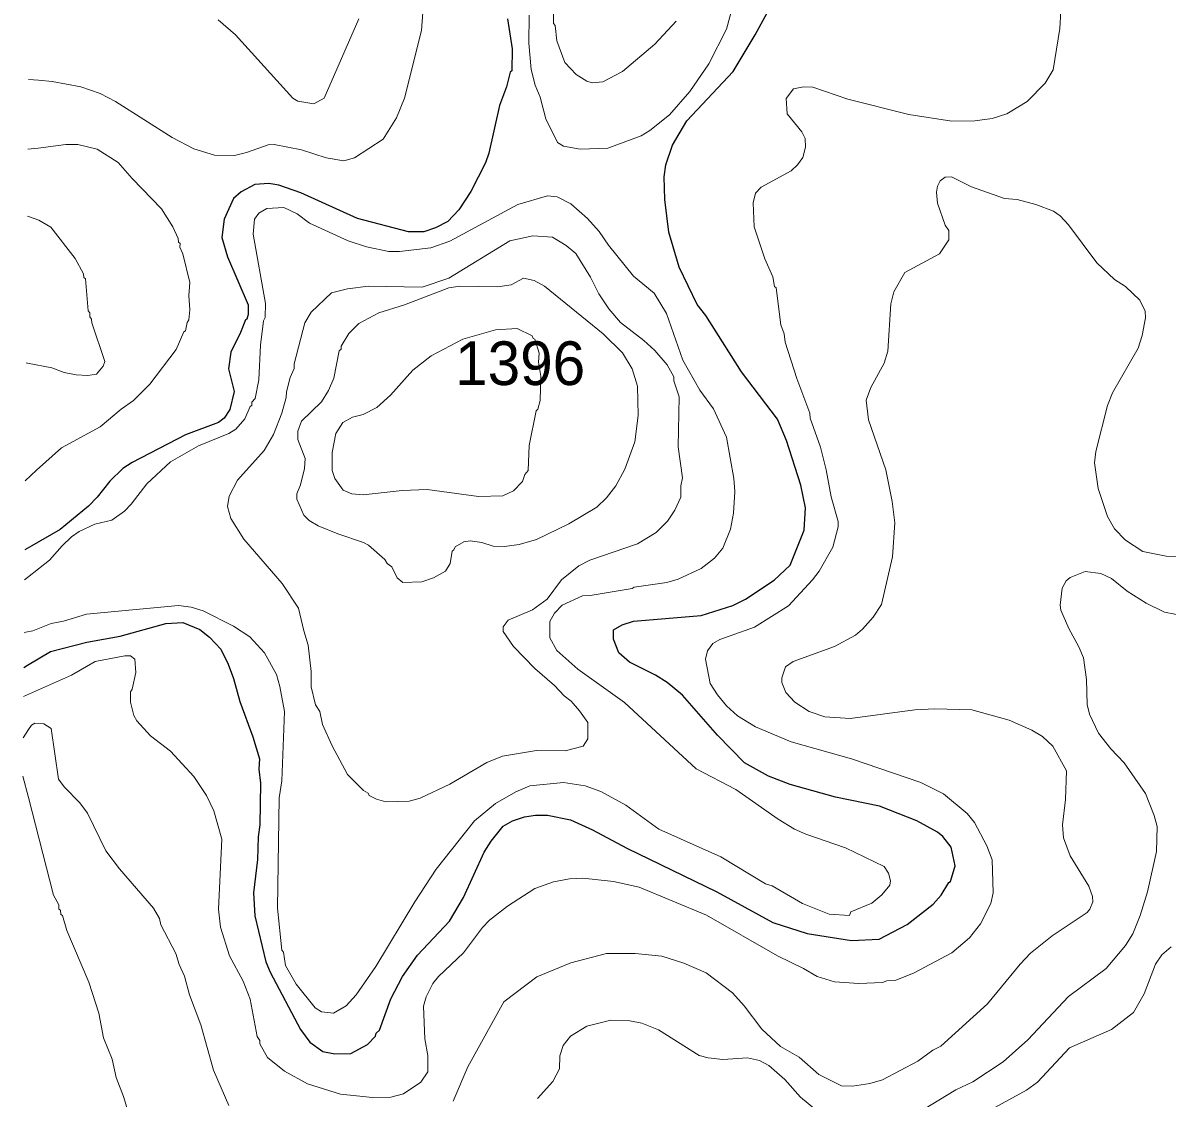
# Model space of a CAD drawing. Extents: x 598.3 to 623.2, y 6902.2 to 6930.1.
# Drawn here: x 598.471 to 600.565, y 6919.535 to 6921.503 of the extents above; entities that cross this region are included whole.
import ezdxf

# ---------------------------------------------------------------- set-up
doc = ezdxf.new("R2010")
doc.units = 0
doc.header["$LTSCALE"] = 0.032
doc.layers.add('1', color=7, linetype='Continuous', lineweight=25)
doc.layers.add('2', color=7, linetype='Continuous', lineweight=13)
doc.layers.add('21', color=7, linetype='Continuous')

msp = doc.modelspace()

# ---------------------------------------------------------------- linework, layer by layer
at = {"layer": '1'}
for points in [[(599.8109, 6921.4817), (599.8655, 6921.5827)], [(599.3574, 6921.5108), (599.3664, 6921.4558), (599.3655, 6921.4154), (599.3623, 6921.413), (599.3559, 6921.3862), (599.3429, 6921.3522), (599.3235, 6921.2647), (599.3172, 6921.2473), (599.2904, 6921.1951), (599.2686, 6921.1611), (599.2484, 6921.1399), (599.2259, 6921.128), (599.2046, 6921.1211), (599.1763, 6921.121), (599.0829, 6921.1452), (598.9791, 6921.1926), (598.9394, 6921.2067), (598.9206, 6921.2094), (598.8952, 6921.2078), (598.8704, 6921.1942), (598.8564, 6921.1818), (598.8389, 6921.1439), (598.8346, 6921.1103), (598.8449, 6921.0753), (598.8831, 6920.9876), (598.8831, 6920.9698), (598.8808, 6920.9614), (598.8783, 6920.9599), (598.8691, 6920.937), (598.851, 6920.9009), (598.8468, 6920.8705), (598.8573, 6920.8288), (598.8496, 6920.796), (598.839, 6920.78), (598.8288, 6920.7719), (598.7681, 6920.7496), (598.6706, 6920.6985), (598.6535, 6920.6875), (598.6297, 6920.6646), (598.6067, 6920.6352), (598.5906, 6920.6191), (598.5388, 6920.5762), (598.4873, 6920.5465), (598.4741, 6920.5389)], [(598.4723, 6920.3238), (598.4791, 6920.3278), (598.5212, 6920.3528), (598.5875, 6920.3701), (598.6486, 6920.3806), (598.7323, 6920.4041), (598.7633, 6920.4056), (598.7943, 6920.3933), (598.8125, 6920.3789), (598.8328, 6920.3571), (598.8465, 6920.3298), (598.8562, 6920.3036), (598.8676, 6920.261), (598.8915, 6920.1968), (598.904, 6920.1561), (598.9026, 6920.1373), (598.9058, 6920.1118), (598.9042, 6920.0354), (598.901, 6920.0133), (598.9001, 6919.9722), (598.8929, 6919.9113), (598.8952, 6919.8692), (598.9154, 6919.785), (598.9232, 6919.766), (598.979, 6919.6611), (598.9958, 6919.6379), (599.0197, 6919.6208), (599.0414, 6919.6164), (599.0707, 6919.6171), (599.1016, 6919.6334), (599.116, 6919.6485), (599.1172, 6919.6543), (599.1231, 6919.6594), (599.1439, 6919.717), (599.1652, 6919.7579), (599.1931, 6919.7968), (599.2516, 6919.8594), (599.2772, 6919.9027), (599.3152, 6919.9852), (599.3279, 6920.0058), (599.3494, 6920.0332), (599.367, 6920.0428), (599.3885, 6920.0503), (599.4089, 6920.0534), (599.4306, 6920.0534), (599.4727, 6920.0444), (599.5132, 6920.0266), (599.576, 6919.9927), (599.7409, 6919.9128), (599.8434, 6919.8566), (599.906, 6919.8366), (599.9869, 6919.8236), (600.0377, 6919.8261), (600.089, 6919.8534), (600.1364, 6919.8903), (600.1515, 6919.9069), (600.1653, 6919.9302), (600.1686, 6919.9316), (600.1766, 6919.9604), (600.1694, 6919.9949), (600.1542, 6920.0144), (600.1448, 6920.022), (600.1065, 6920.0428), (600.0387, 6920.0697), (599.9578, 6920.0859), (599.8752, 6920.1094), (599.835, 6920.1247), (599.7916, 6920.1489), (599.7417, 6920.1998), (599.6778, 6920.273), (599.6498, 6920.2959), (599.6285, 6920.3096), (599.5811, 6920.3333), (599.5615, 6920.3506), (599.5518, 6920.3756), (599.5519, 6920.3925), (599.5677, 6920.4014), (599.5883, 6920.4086), (599.7123, 6920.4186), (599.7703, 6920.437), (599.7932, 6920.4487), (599.8455, 6920.4832), (599.8747, 6920.5109), (599.9006, 6920.5748), (599.903, 6920.6155), (599.8942, 6920.657), (599.8685, 6920.7392), (599.8516, 6920.7781), (599.7859, 6920.8647), (599.7203, 6920.9679), (599.7049, 6920.9882), (599.6718, 6921.0565), (599.653, 6921.1201), (599.6457, 6921.18), (599.6441, 6921.2216), (599.6473, 6921.2437), (599.6594, 6921.2798), (599.6856, 6921.3239), (599.7705, 6921.4145), (599.8109, 6921.4817)]]:
    msp.add_lwpolyline(points, dxfattribs=at)
at = {"layer": '2'}
for points in [[(598.4811, 6921.3996), (598.4993, 6921.3988), (598.524, 6921.3964), (598.5767, 6921.3861), (598.6123, 6921.374), (598.6405, 6921.3598), (598.7441, 6921.2934), (598.7833, 6921.2731), (598.8213, 6921.2613), (598.8578, 6921.2605), (598.8801, 6921.2661), (598.9194, 6921.2805), (598.9307, 6921.2806), (598.9805, 6921.2709), (599.0257, 6921.2563), (599.058, 6921.2507), (599.0777, 6921.2565), (599.1303, 6921.2908), (599.1545, 6921.3298), (599.1694, 6921.3658), (599.2004, 6921.4896), (599.2069, 6921.5804)], [(600.3701, 6921.5249), (600.3686, 6921.493), (600.3563, 6921.4176), (600.3417, 6921.3931), (600.3085, 6921.3597), (600.2717, 6921.3372), (600.2449, 6921.3285), (600.2129, 6921.3244), (600.1709, 6921.3236), (600.0923, 6921.3357), (599.9805, 6921.3641), (599.9166, 6921.3857), (599.8993, 6921.3866), (599.8811, 6921.3828), (599.8675, 6921.3649), (599.8695, 6921.3367), (599.8962, 6921.3038), (599.9022, 6921.2919), (599.9029, 6921.2757), (599.8983, 6921.2568), (599.8886, 6921.2436), (599.8769, 6921.2327), (599.8216, 6921.2025), (599.8116, 6921.1916), (599.8075, 6921.1738), (599.8092, 6921.1299), (599.8285, 6921.0718), (599.8435, 6921.0385), (599.8465, 6921.0208), (599.8495, 6921.0184), (599.8578, 6920.9505), (599.864, 6920.9345), (599.8656, 6920.9189), (599.887, 6920.8527), (599.911, 6920.7891), (599.9113, 6920.7799), (599.9306, 6920.7267), (599.941, 6920.6854), (599.95, 6920.6361), (599.9629, 6920.5909), (599.9629, 6920.5807), (599.953, 6920.5435), (599.928, 6920.5001), (599.9159, 6920.4841), (599.8716, 6920.4365), (599.8097, 6920.3975), (599.746, 6920.3748), (599.7331, 6920.3675), (599.7234, 6920.3538), (599.7202, 6920.3387), (599.7284, 6920.2942), (599.7419, 6920.2734), (599.7587, 6920.2536), (599.7788, 6920.2351), (599.8116, 6920.2148), (599.8766, 6920.1872), (599.987, 6920.1563), (600.1143, 6920.1129), (600.1556, 6920.0923), (600.1987, 6920.0564), (600.2124, 6920.0395), (600.2348, 6919.9971), (600.2445, 6919.9717), (600.2464, 6919.9109), (600.2424, 6919.8917), (600.2235, 6919.8541), (600.203, 6919.8288), (600.171, 6919.8014), (600.1009, 6919.7638), (600.0682, 6919.7515), (600.052, 6919.7499), (600.0439, 6919.7467), (600.0008, 6919.7451), (599.956, 6919.7483), (599.9246, 6919.7578), (599.8993, 6919.7728), (599.8515, 6919.7959), (599.722, 6919.8704), (599.5984, 6919.9216), (599.5515, 6919.9321), (599.4957, 6919.9377), (599.4711, 6919.9369), (599.4419, 6919.9313), (599.4074, 6919.9189), (599.3576, 6919.8869), (599.3247, 6919.8611), (599.3117, 6919.8474)], [(599.397, 6921.5177), (599.3964, 6921.4663), (599.4012, 6921.4183), (599.4084, 6921.3894), (599.4175, 6921.3676), (599.4278, 6921.3279), (599.4492, 6921.2844), (599.4602, 6921.2778), (599.4908, 6921.2725), (599.5411, 6921.274), (599.6021, 6921.297), (599.6179, 6921.3064), (599.6538, 6921.3351), (599.6915, 6921.3776), (599.726, 6921.4287), (599.7587, 6921.4922), (599.7687, 6921.5303)], [(599.4416, 6921.5254), (599.4417, 6921.5025), (599.4448, 6921.4989), (599.4476, 6921.4703), (599.4623, 6921.431), (599.4835, 6921.4087), (599.5029, 6921.3965), (599.5127, 6921.394), (599.5318, 6921.3954), (599.568, 6921.4145), (599.6274, 6921.4647), (599.666, 6921.5065)], [(598.828, 6921.5089), (598.86, 6921.4818), (598.9647, 6921.3657), (598.9739, 6921.3599), (599.0033, 6921.3553), (599.0223, 6921.3659), (599.0856, 6921.5111)], [(598.48, 6921.272), (598.4987, 6921.2743), (598.5494, 6921.2806), (598.5712, 6921.2807), (598.6065, 6921.2724), (598.6449, 6921.2476), (598.6704, 6921.2183), (598.7243, 6921.1633), (598.7453, 6921.1303), (598.7551, 6921.1087), (598.7552, 6921.102), (598.7583, 6921.0998), (598.7577, 6921.093), (598.7632, 6921.0805), (598.7762, 6921.0281), (598.7746, 6921.0042), (598.7763, 6920.9779), (598.7746, 6920.9596), (598.7714, 6920.9553), (598.7683, 6920.9396), (598.7652, 6920.9381), (598.7514, 6920.9055), (598.7029, 6920.8424), (598.6734, 6920.812), (598.6504, 6920.7961), (598.6121, 6920.7643), (598.5411, 6920.7258), (598.4956, 6920.6849), (598.4751, 6920.6654)], [(600.7368, 6920.5253), (600.563, 6920.5271), (600.5205, 6920.5357), (600.4889, 6920.5563), (600.4687, 6920.5775), (600.4556, 6920.5998), (600.4389, 6920.6509), (600.4317, 6920.6979), (600.4341, 6920.7191), (600.4558, 6920.8028), (600.4651, 6920.8263), (600.5117, 6920.9083), (600.5192, 6920.9315), (600.5255, 6920.9638), (600.5247, 6920.976), (600.5149, 6920.996), (600.4889, 6921.021), (600.4686, 6921.0339), (600.4359, 6921.0643), (600.3846, 6921.1336), (600.3689, 6921.15), (600.3569, 6921.1589), (600.3246, 6921.1712), (600.2906, 6921.1801), (600.2671, 6921.1819), (600.2069, 6921.2032), (600.1701, 6921.2215), (600.1587, 6921.2209), (600.1492, 6921.2141), (600.1444, 6921.2047), (600.1426, 6921.1933), (600.1443, 6921.1736), (600.1588, 6921.1333), (600.1653, 6921.1233), (600.1653, 6921.1061), (600.1485, 6921.081), (600.0847, 6921.0468), (600.0646, 6921.0109), (600.0592, 6920.9889), (600.0535, 6920.9028), (600.0471, 6920.8807), (600.0223, 6920.836), (600.014, 6920.8127), (600.0185, 6920.777), (600.0503, 6920.6851), (600.0619, 6920.6271), (600.0665, 6920.5883), (600.062, 6920.5261)], [(598.4736, 6920.4838), (598.4792, 6920.4882), (598.5197, 6920.5198), (598.5423, 6920.5465), (598.5594, 6920.5628), (598.5737, 6920.5722), (598.6025, 6920.5859), (598.6337, 6920.5934), (598.6567, 6920.6099), (598.6691, 6920.6223), (598.6977, 6920.6597), (598.7406, 6920.7002), (598.7918, 6920.7291), (598.8475, 6920.752), (598.8603, 6920.76), (598.8766, 6920.7787), (598.8864, 6920.8012), (598.8895, 6920.8033), (598.8896, 6920.8094), (598.896, 6920.8162), (598.9025, 6920.8498), (598.9056, 6920.9138), (598.911, 6920.9583), (598.9139, 6920.964), (598.9146, 6920.9895), (598.8922, 6921.1167), (598.8945, 6921.1443), (598.9027, 6921.1551), (598.9172, 6921.1636), (598.9483, 6921.1656), (598.9727, 6921.1537), (598.9954, 6921.137), (599.0663, 6921.1048), (599.0998, 6921.0937), (599.1403, 6921.0848), (599.16, 6921.0847), (599.2172, 6921.0914), (599.2521, 6921.104), (599.3763, 6921.1711), (599.4311, 6921.1867), (599.4484, 6921.185), (599.4734, 6921.1722), (599.5041, 6921.1453), (599.5252, 6921.1218), (599.5422, 6921.0967), (599.5883, 6921.04), (599.6262, 6921.0086), (599.6489, 6920.9712), (599.6787, 6920.8859), (599.7094, 6920.8312), (599.7345, 6920.7969), (599.7587, 6920.7453), (599.7719, 6920.6693), (599.7735, 6920.6458), (599.7712, 6920.6061), (599.7655, 6920.5767), (599.7515, 6920.5422), (599.7363, 6920.5237), (599.7122, 6920.5045), (599.6699, 6920.4852), (599.6492, 6920.4793), (599.5895, 6920.4704), (599.5859, 6920.4679), (599.509, 6920.4552), (599.4951, 6920.4549), (599.4575, 6920.4378), (599.4434, 6920.4229), (599.4352, 6920.4077), (599.4352, 6920.3776), (599.4478, 6920.3549), (599.4862, 6920.3204), (599.5716, 6920.2594), (599.7026, 6920.138), (599.7754, 6920.1003), (599.8529, 6920.0458), (599.8829, 6920.0278), (599.9033, 6920.0185), (599.9765, 6919.9933), (600.0469, 6919.9595), (600.0549, 6919.9472), (600.0583, 6919.933), (600.0573, 6919.925), (600.0425, 6919.9071), (600.0243, 6919.8922), (599.9859, 6919.8762), (599.9838, 6919.8698), (599.9465, 6919.8722), (599.8977, 6919.8918), (599.8418, 6919.9238), (599.8297, 6919.9274), (599.7479, 6919.9772), (599.6345, 6920.0277), (599.5739, 6920.0716), (599.5286, 6920.0966), (599.4997, 6920.1069), (599.46, 6920.1133), (599.3982, 6920.1067), (599.3726, 6920.0962), (599.3359, 6920.0747), (599.2973, 6920.0426)], [(598.479, 6921.1495), (598.4809, 6921.1488), (598.4997, 6921.1421), (598.5221, 6921.1293), (598.5662, 6921.0724), (598.5818, 6921.0442), (598.582, 6921.0372), (598.5852, 6921.035), (598.5901, 6920.9766), (598.5932, 6920.9727), (598.5933, 6920.9652), (598.5965, 6920.9614), (598.5967, 6920.9544), (598.6209, 6920.8834), (598.6177, 6920.8749), (598.6053, 6920.8603), (598.5894, 6920.8581), (598.5684, 6920.859), (598.5461, 6920.8638), (598.5237, 6920.8718), (598.4792, 6920.8808), (598.4768, 6920.8813)], [(600.062, 6920.5261), (600.0422, 6920.4388), (600.0267, 6920.4159), (600.0076, 6920.3937), (599.9948, 6920.3826), (599.9563, 6920.3617), (599.8804, 6920.3343), (599.8662, 6920.3248), (599.8594, 6920.3047), (599.8594, 6920.2958), (599.8673, 6920.2779), (599.8837, 6920.2601), (599.9098, 6920.2427), (599.9385, 6920.2332), (599.9846, 6920.23), (600.1032, 6920.2461), (600.1394, 6920.2478), (600.2074, 6920.2461), (600.276, 6920.2273), (600.317, 6920.2091), (600.3369, 6920.1975), (600.3555, 6920.1797), (600.3806, 6920.1344), (600.3791, 6920.0816), (600.3733, 6920.0356), (600.3751, 6920.012), (600.3871, 6919.979), (600.4214, 6919.9234), (600.4284, 6919.9045), (600.4291, 6919.8947), (600.4236, 6919.8813), (600.4183, 6919.8751), (600.3547, 6919.8324), (600.315, 6919.8008), (600.2956, 6919.7806), (600.2363, 6919.7076), (600.1509, 6919.6302), (600.1363, 6919.6228), (600.1086, 6919.6027), (600.0437, 6919.5685), (600.0209, 6919.5621), (599.9889, 6919.5574), (599.9688, 6919.5579), (599.9271, 6919.5784), (599.8915, 6919.61), (599.8575, 6919.6295), (599.8232, 6919.6614), (599.7905, 6919.7045), (599.7692, 6919.7282), (599.7215, 6919.7646), (599.6803, 6919.7826), (599.6399, 6919.7952), (599.5912, 6919.8), (599.5386, 6919.8), (599.4734, 6919.7828), (599.4115, 6919.7574), (599.351, 6919.7117), (599.2848, 6919.5926), (599.258, 6919.5295)], [(600.1188, 6919.5146), (600.1781, 6919.5506), (600.2092, 6919.5651), (600.2648, 6919.6019), (600.3097, 6919.6417), (600.3845, 6919.7213), (600.4535, 6919.7725), (600.4889, 6919.8148), (600.5019, 6919.8363), (600.5155, 6919.8695), (600.5288, 6919.9129), (600.5456, 6919.9865), (600.5465, 6920.0327), (600.5413, 6920.0525), (600.5252, 6920.0929), (600.486, 6920.1488), (600.4615, 6920.1749), (600.4393, 6920.2035), (600.4225, 6920.2382), (600.4187, 6920.2558), (600.417, 6920.3017), (600.4115, 6920.3414), (600.4032, 6920.3614), (600.3847, 6920.395), (600.3704, 6920.4284), (600.3688, 6920.4378), (600.3725, 6920.4689), (600.3801, 6920.4819), (600.3875, 6920.4883), (600.4146, 6920.4994), (600.4433, 6920.4956), (600.4632, 6920.4865), (600.4918, 6920.4634)], [(600.4918, 6920.4634), (600.5263, 6920.4412), (600.5603, 6920.425), (600.5976, 6920.4174)], [(599.2973, 6920.0426), (599.227, 6919.9545), (599.1881, 6919.8946), (599.1169, 6919.7764), (599.0807, 6919.7241), (599.0622, 6919.704), (599.0393, 6919.6909), (599.0171, 6919.6931), (599.0054, 6919.7005), (598.9707, 6919.744), (598.9511, 6919.7783), (598.9478, 6919.8022), (598.9447, 6919.8061), (598.9366, 6919.8829), (598.9398, 6920.0852), (598.9446, 6920.116), (598.9494, 6920.2429), (598.9412, 6920.2888), (598.9349, 6920.3107), (598.9131, 6920.3506), (598.8861, 6920.3799), (598.8559, 6920.3989), (598.8006, 6920.4274), (598.7784, 6920.4338), (598.7558, 6920.4371), (598.5871, 6920.421), (598.545, 6920.4081), (598.5223, 6920.404), (598.4887, 6920.3905), (598.476, 6920.3879), (598.4728, 6920.3872)], [(599.3117, 6919.8474), (599.2768, 6919.8014), (599.2312, 6919.7579), (599.221, 6919.7449), (599.2088, 6919.7205), (599.2037, 6919.7037), (599.2061, 6919.6439), (599.2117, 6919.6135), (599.2118, 6919.5834), (599.1993, 6919.5643), (599.1675, 6919.5432), (599.1443, 6919.5371), (599.1105, 6919.5363), (599.0518, 6919.5426), (598.9918, 6919.5613), (598.9493, 6919.5849), (598.9182, 6919.6096), (598.9042, 6919.6345), (598.9041, 6919.6406), (598.8993, 6919.6481), (598.8864, 6919.7165), (598.874, 6919.7494), (598.8488, 6919.7958), (598.8321, 6919.8481), (598.8289, 6919.8811), (598.8345, 6920.0094), (598.82, 6920.0613), (598.8069, 6920.0893), (598.7835, 6920.1238), (598.741, 6920.1704), (598.7044, 6920.1982), (598.6793, 6920.2257), (598.6739, 6920.2355), (598.6678, 6920.2602), (598.6677, 6920.2791), (598.671, 6920.284), (598.6775, 6920.3144), (598.6758, 6920.3389), (598.6674, 6920.3448), (598.6575, 6920.3448), (598.603, 6920.3343), (598.5596, 6920.3094), (598.4776, 6920.2729), (598.4719, 6920.2703)], [(598.8474, 6919.5219), (598.8198, 6919.5862), (598.7965, 6919.6695), (598.7756, 6919.7242), (598.7666, 6919.7586), (598.7567, 6919.7801), (598.7509, 6919.7999), (598.723, 6919.8525), (598.721, 6919.864), (598.7099, 6919.8827), (598.6475, 6919.9549), (598.6225, 6919.9878), (598.5892, 6920.0567), (598.5748, 6920.0759), (598.5465, 6920.105), (598.536, 6920.119), (598.5227, 6920.2121), (598.5089, 6920.2202), (598.4927, 6920.2219), (598.4862, 6920.2182), (598.4809, 6920.2098), (598.4712, 6920.1945)], [(598.4707, 6920.1247), (598.4808, 6920.0854), (598.5268, 6919.9067), (598.5365, 6919.8894), (598.5367, 6919.8813), (598.5398, 6919.8792), (598.5399, 6919.8716), (598.5431, 6919.8694), (598.5509, 6919.8421), (598.5917, 6919.7473), (598.6095, 6919.6906), (598.618, 6919.6456), (598.6338, 6919.6064), (598.6417, 6919.5732), (598.6549, 6919.5384), (598.6874, 6919.4312)], [(600.5725, 6919.8122), (600.5554, 6919.7976), (600.5436, 6919.7804), (600.5229, 6919.7259), (600.5033, 6919.6922), (600.4628, 6919.6609), (600.386, 6919.6271), (600.3276, 6919.5642), (600.3076, 6919.5498), (600.2428, 6919.5142)], [(599.4128, 6919.5343), (599.4404, 6919.5656), (599.4529, 6919.5892), (599.4531, 6919.6125), (599.4592, 6919.6319), (599.4732, 6919.6487), (599.5025, 6919.6669), (599.5467, 6919.6778), (599.5812, 6919.677), (599.6033, 6919.6722), (599.6338, 6919.6603), (599.7081, 6919.6136), (599.7249, 6919.6089), (599.7519, 6919.6059), (599.7968, 6919.609), (599.8186, 6919.6043), (599.8361, 6919.5952), (599.8651, 6919.5693), (599.8939, 6919.5372), (599.9219, 6919.5139)]]:
    msp.add_lwpolyline(points, dxfattribs=at)
for points in [[(599.1177, 6920.0823), (599.1043, 6920.089), (599.1029, 6920.0932), (599.094, 6920.0983), (599.0648, 6920.1274), (599.0367, 6920.18), (599.0189, 6920.2189), (599.0141, 6920.243), (599.0064, 6920.2553), (598.9981, 6920.288), (598.998, 6920.316), (598.9931, 6920.3643), (598.9846, 6920.3904), (598.9753, 6920.4321), (598.945, 6920.4772), (598.8753, 6920.5582), (598.851, 6920.5961), (598.8451, 6920.6183), (598.8481, 6920.6374), (598.8636, 6920.6662), (598.9122, 6920.7205), (598.9295, 6920.7502), (598.9447, 6920.7888), (598.9527, 6920.8176), (598.9529, 6920.8279), (598.96, 6920.8546), (598.9672, 6920.8711), (598.9674, 6920.8796), (598.987, 6920.9542), (598.9982, 6920.9742), (599.0354, 6921.0093), (599.0647, 6921.0168), (599.1033, 6921.0216), (599.2014, 6921.0199), (599.2504, 6921.036), (599.3618, 6921.1042), (599.4042, 6921.1138), (599.44, 6921.1114), (599.4649, 6921.0962), (599.4825, 6921.0811), (599.5096, 6921.0378), (599.5249, 6921.0073), (599.5428, 6920.9803), (599.5642, 6920.9549), (599.6072, 6920.9221), (599.6272, 6920.904), (599.6496, 6920.8775), (599.6618, 6920.8553), (599.6619, 6920.8484), (599.6715, 6920.8192), (599.67, 6920.7277), (599.6781, 6920.6707), (599.6748, 6920.6563), (599.6747, 6920.6356), (599.6639, 6920.6113), (599.6506, 6920.5912), (599.6299, 6920.5705), (599.5957, 6920.5497), (599.5083, 6920.5198), (599.4884, 6920.5099), (599.4564, 6920.4842), (599.4301, 6920.4484), (599.4034, 6920.4289), (599.359, 6920.4103), (599.3494, 6920.3982), (599.3498, 6920.3894), (599.3683, 6920.3618), (599.4074, 6920.3215), (599.4438, 6920.2908), (599.4616, 6920.2714), (599.4739, 6920.2616), (599.4893, 6920.2445), (599.5045, 6920.2227), (599.5047, 6920.193), (599.4958, 6920.1798), (599.4634, 6920.1707), (599.4104, 6920.1716), (599.3483, 6920.1613), (599.3195, 6920.1494), (599.252, 6920.11), (599.1978, 6920.0842), (599.1779, 6920.079), (599.1351, 6920.0778)], [(599.1461, 6920.5075), (599.1374, 6920.5141), (599.1331, 6920.5215), (599.1035, 6920.5473), (599.0943, 6920.5525), (599.0469, 6920.5681), (599.0111, 6920.583), (598.9946, 6920.5927), (598.9851, 6920.6024), (598.9722, 6920.6314), (598.9722, 6920.6414), (598.9788, 6920.6579), (598.9858, 6920.6876), (598.9874, 6920.706), (598.9738, 6920.741), (598.9738, 6920.7564), (598.9803, 6920.7745), (599.0171, 6920.8098), (599.0302, 6920.8306), (599.04, 6920.853), (599.0498, 6920.9031), (599.053, 6920.9061), (599.0531, 6920.912), (599.0672, 6920.9347), (599.0855, 6920.9532), (599.1221, 6920.9726), (599.1694, 6920.9875), (599.25, 6921.0186), (599.2706, 6921.0217), (599.3402, 6921.02), (599.3642, 6921.024), (599.3868, 6921.036), (599.4066, 6921.0319), (599.4254, 6921.0216), (599.5328, 6920.9345), (599.5678, 6920.8996), (599.5858, 6920.87), (599.5954, 6920.8386), (599.597, 6920.7847), (599.5905, 6920.7367), (599.5726, 6920.6863), (599.5559, 6920.656), (599.5391, 6920.6343), (599.5213, 6920.6173), (599.4697, 6920.5864), (599.4107, 6920.5576), (599.3792, 6920.5486), (599.352, 6920.5449), (599.3313, 6920.5457), (599.3105, 6920.5521), (599.2894, 6920.5553), (599.2778, 6920.5538), (599.2616, 6920.5444), (599.2596, 6920.5386), (599.2563, 6920.5365), (599.2524, 6920.5138), (599.2443, 6920.4997), (599.222, 6920.4876), (599.2011, 6920.4806), (599.1661, 6920.4792), (599.1556, 6920.4879)], [(599.3752, 6920.9438), (599.4026, 6920.9309), (599.4044, 6920.9256), (599.4077, 6920.9248), (599.4157, 6920.8986), (599.4142, 6920.8823), (599.4189, 6920.8568), (599.4172, 6920.8122), (599.4134, 6920.7963), (599.41, 6920.7933), (599.3971, 6920.7299), (599.3954, 6920.6844), (599.3895, 6920.6769), (599.3849, 6920.6639), (599.3685, 6920.6467), (599.3489, 6920.638), (599.3046, 6920.6363), (599.2107, 6920.6492), (599.1646, 6920.6476), (599.0935, 6920.6395), (599.0728, 6920.6412), (599.057, 6920.6479), (599.0415, 6920.6693), (599.0368, 6920.6842), (599.037, 6920.7173), (599.0434, 6920.7518), (599.0562, 6920.772), (599.0739, 6920.7818), (599.0937, 6920.7869), (599.1187, 6920.7995), (599.1434, 6920.8221), (599.1844, 6920.868), (599.2179, 6920.894), (599.2757, 6920.9244), (599.3354, 6920.9415)]]:
    msp.add_lwpolyline(points, close=True, dxfattribs=at)

# ---------------------------------------------------------------- texts
at = {"layer": '21'}
msp.add_text('1396', height=0.08, dxfattribs=at).set_placement((599.2618, 6920.8405))

doc.saveas('drawing.dxf')
